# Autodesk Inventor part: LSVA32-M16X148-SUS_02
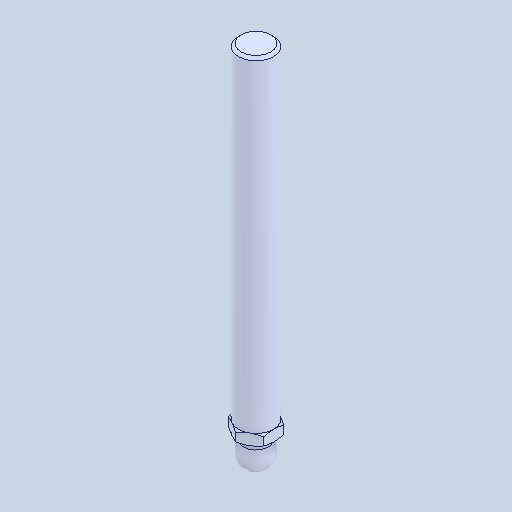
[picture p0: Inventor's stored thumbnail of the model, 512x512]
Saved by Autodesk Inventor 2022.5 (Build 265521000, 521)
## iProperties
Created: 2024-08
Part Number: LSVA32-M16X148-SUS_02
Material: 一般
Document SubType Name: Modeling
Designer: ImaoCorp
Density: 1 g/cm^3
Appearance: 既定
Author: ImaoCorp
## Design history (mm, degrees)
feature "LSVA32-M16X148-SUS_02"
node "ソリッド1"
